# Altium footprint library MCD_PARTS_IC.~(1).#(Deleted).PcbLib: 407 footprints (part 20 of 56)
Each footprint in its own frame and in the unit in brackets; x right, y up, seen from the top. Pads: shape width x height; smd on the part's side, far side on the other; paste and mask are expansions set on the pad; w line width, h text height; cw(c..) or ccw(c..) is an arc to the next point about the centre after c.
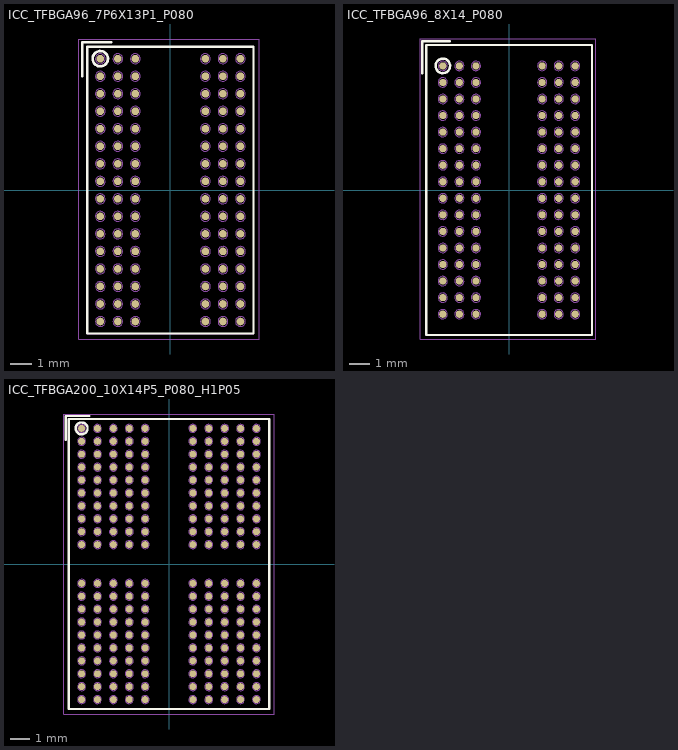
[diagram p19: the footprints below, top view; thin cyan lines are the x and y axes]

## ICC_TFBGA96_7P6X13P1_P080 [mm] "MCD-02775"
height 1.1
pads (96):
  round 0.35 smd mask+0.05: A1(-3.2,6) A2(-2.4,6) A3(-1.6,6) A7(1.6,6) A8(2.4,6) A9(3.2,6) B1(-3.2,5.2) B2(-2.4,5.2) B3(-1.6,5.2) B7(1.6,5.2) B8(2.4,5.2) B9(3.2,5.2) C1(-3.2,4.4) C2(-2.4,4.4) C3(-1.6,4.4) C7(1.6,4.4) C8(2.4,4.4) C9(3.2,4.4) D1(-3.2,3.6) D2(-2.4,3.6) D3(-1.6,3.6) D7(1.6,3.6) D8(2.4,3.6) D9(3.2,3.6) E1(-3.2,2.8) E2(-2.4,2.8) E3(-1.6,2.8) E7(1.6,2.8) E8(2.4,2.8) E9(3.2,2.8) F1(-3.2,2) F2(-2.4,2) F3(-1.6,2) F7(1.6,2) F8(2.4,2) F9(3.2,2) G1(-3.2,1.2) G2(-2.4,1.2) G3(-1.6,1.2) G7(1.6,1.2) G8(2.4,1.2) G9(3.2,1.2) H1(-3.2,0.4) H2(-2.4,0.4) H3(-1.6,0.4) H7(1.6,0.4) H8(2.4,0.4) H9(3.2,0.4) J1(-3.2,-0.4) J2(-2.4,-0.4) J3(-1.6,-0.4) J7(1.6,-0.4) J8(2.4,-0.4) J9(3.2,-0.4) K1(-3.2,-1.2) K2(-2.4,-1.2) K3(-1.6,-1.2) K7(1.6,-1.2) K8(2.4,-1.2) K9(3.2,-1.2) L1(-3.2,-2) L2(-2.4,-2) L3(-1.6,-2) L7(1.6,-2) L8(2.4,-2) L9(3.2,-2) M1(-3.2,-2.8) M2(-2.4,-2.8) M3(-1.6,-2.8) M7(1.6,-2.8) M8(2.4,-2.8) M9(3.2,-2.8) N1(-3.2,-3.6) N2(-2.4,-3.6) N3(-1.6,-3.6) N7(1.6,-3.6) N8(2.4,-3.6) N9(3.2,-3.6) P1(-3.2,-4.4) P2(-2.4,-4.4) P3(-1.6,-4.4) P7(1.6,-4.4) P8(2.4,-4.4) P9(3.2,-4.4) R1(-3.2,-5.2) R2(-2.4,-5.2) R3(-1.6,-5.2) R7(1.6,-5.2) R8(2.4,-5.2) R9(3.2,-5.2) T1(-3.2,-6) T2(-2.4,-6) T3(-1.6,-6) T7(1.6,-6) T8(2.4,-6) T9(3.2,-6)
Top Overlay:
  lines w0.1: -3.8,-6.55 -3.8,6.55 3.8,6.55 3.8,-6.55 -3.8,-6.55
  lines w0.12: -4.025,5.2 -4.025,6.75 -2.7,6.75 ; -2.851,6.023 ccw(c-3.2,6) -2.85,6
M14-Top Assembly:
  circle w0.01: c-3.2,6 r0.35
  circle w0.01: c-3.2,6 r0.225
  circle w0.01: c-2.4,6 r0.225
  circle w0.01: c-1.6,6 r0.225
  circle w0.01: c-3.2,-5.2 r0.225
  circle w0.01: c-2.4,-5.2 r0.225
  circle w0.01: c-1.6,-5.2 r0.225
  circle w0.01: c-1.6,-4.4 r0.225
  circle w0.01: c-2.4,-4.4 r0.225
  circle w0.01: c-3.2,-4.4 r0.225
  circle w0.01: c-1.6,-3.6 r0.225
  circle w0.01: c-2.4,-3.6 r0.225
  circle w0.01: c-3.2,-3.6 r0.225
  circle w0.01: c-1.6,-2.8 r0.225
  circle w0.01: c-2.4,-2.8 r0.225
  circle w0.01: c-3.2,-2.8 r0.225
  circle w0.01: c-1.6,-2 r0.225
  circle w0.01: c-2.4,-2 r0.225
  circle w0.01: c-3.2,-2 r0.225
  circle w0.01: c-1.6,-1.2 r0.225
  circle w0.01: c-2.4,-1.2 r0.225
  circle w0.01: c-3.2,-1.2 r0.225
  circle w0.01: c-1.6,-0.4 r0.225
  circle w0.01: c-2.4,-0.4 r0.225
  circle w0.01: c-3.2,-0.4 r0.225
  circle w0.01: c-1.6,0.4 r0.225
  circle w0.01: c-2.4,0.4 r0.225
  circle w0.01: c-3.2,0.4 r0.225
  circle w0.01: c-1.6,1.2 r0.225
  circle w0.01: c-2.4,1.2 r0.225
  circle w0.01: c-3.2,1.2 r0.225
  circle w0.01: c-1.6,2 r0.225
  circle w0.01: c-2.4,2 r0.225
  circle w0.01: c-3.2,2 r0.225
  circle w0.01: c-1.6,2.8 r0.225
  circle w0.01: c-2.4,2.8 r0.225
  circle w0.01: c-3.2,2.8 r0.225
  circle w0.01: c-1.6,3.6 r0.225
  circle w0.01: c-2.4,3.6 r0.225
  circle w0.01: c-3.2,3.6 r0.225
  circle w0.01: c-1.6,4.4 r0.225
  circle w0.01: c-2.4,4.4 r0.225
  circle w0.01: c-3.2,4.4 r0.225
  circle w0.01: c-1.6,5.2 r0.225
  circle w0.01: c-2.4,5.2 r0.225
  circle w0.01: c-3.2,5.2 r0.225
  circle w0.01: c1.6,6 r0.225
  circle w0.01: c2.4,6 r0.225
  circle w0.01: c3.2,6 r0.225
  circle w0.01: c1.6,-5.2 r0.225
  circle w0.01: c2.4,-5.2 r0.225
  circle w0.01: c3.2,-5.2 r0.225
  circle w0.01: c3.2,-4.4 r0.225
  circle w0.01: c2.4,-4.4 r0.225
  circle w0.01: c1.6,-4.4 r0.225
  circle w0.01: c3.2,-3.6 r0.225
  circle w0.01: c2.4,-3.6 r0.225
  circle w0.01: c1.6,-3.6 r0.225
  circle w0.01: c3.2,-2.8 r0.225
  circle w0.01: c2.4,-2.8 r0.225
  circle w0.01: c1.6,-2.8 r0.225
  circle w0.01: c3.2,-2 r0.225
  circle w0.01: c2.4,-2 r0.225
  circle w0.01: c1.6,-2 r0.225
  circle w0.01: c3.2,-1.2 r0.225
  circle w0.01: c2.4,-1.2 r0.225
  circle w0.01: c1.6,-1.2 r0.225
  circle w0.01: c3.2,-0.4 r0.225
  circle w0.01: c2.4,-0.4 r0.225
  circle w0.01: c1.6,-0.4 r0.225
  circle w0.01: c3.2,0.4 r0.225
  circle w0.01: c2.4,0.4 r0.225
  circle w0.01: c1.6,0.4 r0.225
  circle w0.01: c3.2,1.2 r0.225
  circle w0.01: c2.4,1.2 r0.225
  circle w0.01: c1.6,1.2 r0.225
  circle w0.01: c3.2,2 r0.225
  circle w0.01: c2.4,2 r0.225
  circle w0.01: c1.6,2 r0.225
  circle w0.01: c3.2,2.8 r0.225
  circle w0.01: c2.4,2.8 r0.225
  circle w0.01: c1.6,2.8 r0.225
  circle w0.01: c3.2,3.6 r0.225
  circle w0.01: c2.4,3.6 r0.225
  circle w0.01: c1.6,3.6 r0.225
  circle w0.01: c3.2,4.4 r0.225
  circle w0.01: c2.4,4.4 r0.225
  circle w0.01: c1.6,4.4 r0.225
  circle w0.01: c3.2,5.2 r0.225
  circle w0.01: c2.4,5.2 r0.225
  circle w0.01: c1.6,5.2 r0.225
  circle w0.01: c3.2,-6 r0.225
  circle w0.01: c2.4,-6 r0.225
  circle w0.01: c1.6,-6 r0.225
  circle w0.01: c-1.6,-6 r0.225
  circle w0.01: c-2.4,-6 r0.225
  circle w0.01: c-3.2,-6 r0.225
  lines w0.01: -3.8,-6.55 -3.8,6.55 3.8,6.55 3.8,-6.55 -3.8,-6.55
  text "'.Designator'" at -2,-0.5 h0.75
  text "A1" at -3.575,5.8 h0.75
M16-Top Courtyard:
  lines w0.01: -4.175,-6.8 4.05,-6.8 4.05,6.9 -4.175,6.9 -4.175,-6.8
3D body: height 1.21, standoff 1.2, extent -3.448,5.751 -2.95,6.25
3D body: height 1.2, standoff 0.4, extent -3.8,-6.55 3.8,6.55
3D body: height 0.5, standoff 0, extent -3.45,5.754 -2.95,6.246
3D body: height 0.5, standoff 0, extent -2.65,5.754 -2.15,6.246
3D body: height 0.5, standoff 0, extent -1.85,5.754 -1.35,6.246
3D body: height 0.5, standoff 0, extent 1.35,5.754 1.85,6.246
3D body: height 0.5, standoff 0, extent 2.15,5.754 2.65,6.246
3D body: height 0.5, standoff 0, extent 2.95,5.754 3.45,6.246
3D body: height 0.5, standoff 0, extent -3.45,4.954 -2.95,5.446
3D body: height 0.5, standoff 0, extent -2.65,4.954 -2.15,5.446
3D body: height 0.5, standoff 0, extent -1.85,4.954 -1.35,5.446
3D body: height 0.5, standoff 0, extent 1.35,4.954 1.85,5.446
3D body: height 0.5, standoff 0, extent 2.15,4.954 2.65,5.446
3D body: height 0.5, standoff 0, extent 2.95,4.954 3.45,5.446
3D body: height 0.5, standoff 0, extent -3.45,4.154 -2.95,4.646
3D body: height 0.5, standoff 0, extent -2.65,4.154 -2.15,4.646
3D body: height 0.5, standoff 0, extent -1.85,4.154 -1.35,4.646
3D body: height 0.5, standoff 0, extent 1.35,4.154 1.85,4.646
3D body: height 0.5, standoff 0, extent 2.15,4.154 2.65,4.646
3D body: height 0.5, standoff 0, extent 2.95,4.154 3.45,4.646
3D body: height 0.5, standoff 0, extent -3.45,3.354 -2.95,3.846
3D body: height 0.5, standoff 0, extent -2.65,3.354 -2.15,3.846
3D body: height 0.5, standoff 0, extent -1.85,3.354 -1.35,3.846
3D body: height 0.5, standoff 0, extent 1.35,3.354 1.85,3.846
3D body: height 0.5, standoff 0, extent 2.15,3.354 2.65,3.846
3D body: height 0.5, standoff 0, extent 2.95,3.354 3.45,3.846
3D body: height 0.5, standoff 0, extent -3.45,2.554 -2.95,3.046
3D body: height 0.5, standoff 0, extent -2.65,2.554 -2.15,3.046
3D body: height 0.5, standoff 0, extent -1.85,2.554 -1.35,3.046
3D body: height 0.5, standoff 0, extent 1.35,2.554 1.85,3.046
3D body: height 0.5, standoff 0, extent 2.15,2.554 2.65,3.046
3D body: height 0.5, standoff 0, extent 2.95,2.554 3.45,3.046
3D body: height 0.5, standoff 0, extent -3.45,1.754 -2.95,2.246
3D body: height 0.5, standoff 0, extent -2.65,1.754 -2.15,2.246
3D body: height 0.5, standoff 0, extent -1.85,1.754 -1.35,2.246
3D body: height 0.5, standoff 0, extent 1.35,1.754 1.85,2.246
3D body: height 0.5, standoff 0, extent 2.15,1.754 2.65,2.246
3D body: height 0.5, standoff 0, extent 2.95,1.754 3.45,2.246
3D body: height 0.5, standoff 0, extent -3.45,0.954 -2.95,1.446
3D body: height 0.5, standoff 0, extent -2.65,0.954 -2.15,1.446
3D body: height 0.5, standoff 0, extent -1.85,0.954 -1.35,1.446
3D body: height 0.5, standoff 0, extent 1.35,0.954 1.85,1.446
3D body: height 0.5, standoff 0, extent 2.15,0.954 2.65,1.446
3D body: height 0.5, standoff 0, extent 2.95,0.954 3.45,1.446
3D body: height 0.5, standoff 0, extent -3.45,0.154 -2.95,0.646
3D body: height 0.5, standoff 0, extent -2.65,0.154 -2.15,0.646
3D body: height 0.5, standoff 0, extent -1.85,0.154 -1.35,0.646
3D body: height 0.5, standoff 0, extent 1.35,0.154 1.85,0.646
3D body: height 0.5, standoff 0, extent 2.15,0.154 2.65,0.646
3D body: height 0.5, standoff 0, extent 2.95,0.154 3.45,0.646
3D body: height 0.5, standoff 0, extent -3.45,-0.646 -2.95,-0.154
3D body: height 0.5, standoff 0, extent -2.65,-0.646 -2.15,-0.154
3D body: height 0.5, standoff 0, extent -1.85,-0.646 -1.35,-0.154
3D body: height 0.5, standoff 0, extent 1.35,-0.646 1.85,-0.154
3D body: height 0.5, standoff 0, extent 2.15,-0.646 2.65,-0.154
3D body: height 0.5, standoff 0, extent 2.95,-0.646 3.45,-0.154
3D body: height 0.5, standoff 0, extent -3.45,-1.446 -2.95,-0.954
3D body: height 0.5, standoff 0, extent -2.65,-1.446 -2.15,-0.954
3D body: height 0.5, standoff 0, extent -1.85,-1.446 -1.35,-0.954
3D body: height 0.5, standoff 0, extent 1.35,-1.446 1.85,-0.954
3D body: height 0.5, standoff 0, extent 2.15,-1.446 2.65,-0.954
3D body: height 0.5, standoff 0, extent 2.95,-1.446 3.45,-0.954
3D body: height 0.5, standoff 0, extent -3.45,-2.246 -2.95,-1.754
3D body: height 0.5, standoff 0, extent -2.65,-2.246 -2.15,-1.754
3D body: height 0.5, standoff 0, extent -1.85,-2.246 -1.35,-1.754
3D body: height 0.5, standoff 0, extent 1.35,-2.246 1.85,-1.754
3D body: height 0.5, standoff 0, extent 2.15,-2.246 2.65,-1.754
3D body: height 0.5, standoff 0, extent 2.95,-2.246 3.45,-1.754
3D body: height 0.5, standoff 0, extent -3.45,-3.046 -2.95,-2.554
3D body: height 0.5, standoff 0, extent -2.65,-3.046 -2.15,-2.554
3D body: height 0.5, standoff 0, extent -1.85,-3.046 -1.35,-2.554
3D body: height 0.5, standoff 0, extent 1.35,-3.046 1.85,-2.554
3D body: height 0.5, standoff 0, extent 2.15,-3.046 2.65,-2.554
3D body: height 0.5, standoff 0, extent 2.95,-3.046 3.45,-2.554
3D body: height 0.5, standoff 0, extent -3.45,-3.846 -2.95,-3.354
3D body: height 0.5, standoff 0, extent -2.65,-3.846 -2.15,-3.354
3D body: height 0.5, standoff 0, extent -1.85,-3.846 -1.35,-3.354
3D body: height 0.5, standoff 0, extent 1.35,-3.846 1.85,-3.354
3D body: height 0.5, standoff 0, extent 2.15,-3.846 2.65,-3.354
3D body: height 0.5, standoff 0, extent 2.95,-3.846 3.45,-3.354
3D body: height 0.5, standoff 0, extent -3.45,-4.646 -2.95,-4.154
3D body: height 0.5, standoff 0, extent -2.65,-4.646 -2.15,-4.154
3D body: height 0.5, standoff 0, extent -1.85,-4.646 -1.35,-4.154
3D body: height 0.5, standoff 0, extent 1.35,-4.646 1.85,-4.154
3D body: height 0.5, standoff 0, extent 2.15,-4.646 2.65,-4.154
3D body: height 0.5, standoff 0, extent 2.95,-4.646 3.45,-4.154
3D body: height 0.5, standoff 0, extent -3.45,-5.446 -2.95,-4.954
3D body: height 0.5, standoff 0, extent -2.65,-5.446 -2.15,-4.954
3D body: height 0.5, standoff 0, extent -1.85,-5.446 -1.35,-4.954
3D body: height 0.5, standoff 0, extent 1.35,-5.446 1.85,-4.954
3D body: height 0.5, standoff 0, extent 2.15,-5.446 2.65,-4.954
3D body: height 0.5, standoff 0, extent 2.95,-5.446 3.45,-4.954
3D body: height 0.5, standoff 0, extent -3.45,-6.246 -2.95,-5.754
3D body: height 0.5, standoff 0, extent -2.65,-6.246 -2.15,-5.754
3D body: height 0.5, standoff 0, extent -1.85,-6.246 -1.35,-5.754
3D body: height 0.5, standoff 0, extent 1.35,-6.246 1.85,-5.754
3D body: height 0.5, standoff 0, extent 2.15,-6.246 2.65,-5.754
3D body: height 0.5, standoff 0, extent 2.95,-6.246 3.45,-5.754

## ICC_TFBGA96_8X14_P080 [mm] "MCD-02181"
height 1.1
pads (96):
  round 0.35 smd mask+0.05: A1(-3.2,6) A2(-2.4,6) A3(-1.6,6) A7(1.6,6) A8(2.4,6) A9(3.2,6) B1(-3.2,5.2) B2(-2.4,5.2) B3(-1.6,5.2) B7(1.6,5.2) B8(2.4,5.2) B9(3.2,5.2) C1(-3.2,4.4) C2(-2.4,4.4) C3(-1.6,4.4) C7(1.6,4.4) C8(2.4,4.4) C9(3.2,4.4) D1(-3.2,3.6) D2(-2.4,3.6) D3(-1.6,3.6) D7(1.6,3.6) D8(2.4,3.6) D9(3.2,3.6) E1(-3.2,2.8) E2(-2.4,2.8) E3(-1.6,2.8) E7(1.6,2.8) E8(2.4,2.8) E9(3.2,2.8) F1(-3.2,2) F2(-2.4,2) F3(-1.6,2) F7(1.6,2) F8(2.4,2) F9(3.2,2) G1(-3.2,1.2) G2(-2.4,1.2) G3(-1.6,1.2) G7(1.6,1.2) G8(2.4,1.2) G9(3.2,1.2) H1(-3.2,0.4) H2(-2.4,0.4) H3(-1.6,0.4) H7(1.6,0.4) H8(2.4,0.4) H9(3.2,0.4) J1(-3.2,-0.4) J2(-2.4,-0.4) J3(-1.6,-0.4) J7(1.6,-0.4) J8(2.4,-0.4) J9(3.2,-0.4) K1(-3.2,-1.2) K2(-2.4,-1.2) K3(-1.6,-1.2) K7(1.6,-1.2) K8(2.4,-1.2) K9(3.2,-1.2) L1(-3.2,-2) L2(-2.4,-2) L3(-1.6,-2) L7(1.6,-2) L8(2.4,-2) L9(3.2,-2) M1(-3.2,-2.8) M2(-2.4,-2.8) M3(-1.6,-2.8) M7(1.6,-2.8) M8(2.4,-2.8) M9(3.2,-2.8) N1(-3.2,-3.6) N2(-2.4,-3.6) N3(-1.6,-3.6) N7(1.6,-3.6) N8(2.4,-3.6) N9(3.2,-3.6) P1(-3.2,-4.4) P2(-2.4,-4.4) P3(-1.6,-4.4) P7(1.6,-4.4) P8(2.4,-4.4) P9(3.2,-4.4) R1(-3.2,-5.2) R2(-2.4,-5.2) R3(-1.6,-5.2) R7(1.6,-5.2) R8(2.4,-5.2) R9(3.2,-5.2) T1(-3.2,-6) T2(-2.4,-6) T3(-1.6,-6) T7(1.6,-6) T8(2.4,-6) T9(3.2,-6)
Top Overlay:
  lines w0.1: -4,-7 -4,7 4,7 4,-7 -4,-7
  lines w0.12: -4.2,5.65 -4.2,7.2 -2.875,7.2 ; -2.851,6.023 ccw(c-3.2,6) -2.85,6
M14-Top Assembly:
  circle w0.01: c-3.2,-6 r0.225
  circle w0.01: c-2.4,-6 r0.225
  circle w0.01: c-1.6,-6 r0.225
  circle w0.01: c1.6,-6 r0.225
  circle w0.01: c2.4,-6 r0.225
  circle w0.01: c3.2,-6 r0.225
  circle w0.01: c1.6,5.2 r0.225
  circle w0.01: c2.4,5.2 r0.225
  circle w0.01: c3.2,5.2 r0.225
  circle w0.01: c1.6,4.4 r0.225
  circle w0.01: c2.4,4.4 r0.225
  circle w0.01: c3.2,4.4 r0.225
  circle w0.01: c1.6,3.6 r0.225
  circle w0.01: c2.4,3.6 r0.225
  circle w0.01: c3.2,3.6 r0.225
  circle w0.01: c1.6,2.8 r0.225
  circle w0.01: c2.4,2.8 r0.225
  circle w0.01: c3.2,2.8 r0.225
  circle w0.01: c1.6,2 r0.225
  circle w0.01: c2.4,2 r0.225
  circle w0.01: c3.2,2 r0.225
  circle w0.01: c1.6,1.2 r0.225
  circle w0.01: c2.4,1.2 r0.225
  circle w0.01: c3.2,1.2 r0.225
  circle w0.01: c1.6,0.4 r0.225
  circle w0.01: c2.4,0.4 r0.225
  circle w0.01: c3.2,0.4 r0.225
  circle w0.01: c1.6,-0.4 r0.225
  circle w0.01: c2.4,-0.4 r0.225
  circle w0.01: c3.2,-0.4 r0.225
  circle w0.01: c1.6,-1.2 r0.225
  circle w0.01: c2.4,-1.2 r0.225
  circle w0.01: c3.2,-1.2 r0.225
  circle w0.01: c1.6,-2 r0.225
  circle w0.01: c2.4,-2 r0.225
  circle w0.01: c3.2,-2 r0.225
  circle w0.01: c1.6,-2.8 r0.225
  circle w0.01: c2.4,-2.8 r0.225
  circle w0.01: c3.2,-2.8 r0.225
  circle w0.01: c1.6,-3.6 r0.225
  circle w0.01: c2.4,-3.6 r0.225
  circle w0.01: c3.2,-3.6 r0.225
  circle w0.01: c1.6,-4.4 r0.225
  circle w0.01: c2.4,-4.4 r0.225
  circle w0.01: c3.2,-4.4 r0.225
  circle w0.01: c3.2,-5.2 r0.225
  circle w0.01: c2.4,-5.2 r0.225
  circle w0.01: c1.6,-5.2 r0.225
  circle w0.01: c3.2,6 r0.225
  circle w0.01: c2.4,6 r0.225
  circle w0.01: c1.6,6 r0.225
  circle w0.01: c-3.2,5.2 r0.225
  circle w0.01: c-2.4,5.2 r0.225
  circle w0.01: c-1.6,5.2 r0.225
  circle w0.01: c-3.2,4.4 r0.225
  circle w0.01: c-2.4,4.4 r0.225
  circle w0.01: c-1.6,4.4 r0.225
  circle w0.01: c-3.2,3.6 r0.225
  circle w0.01: c-2.4,3.6 r0.225
  circle w0.01: c-1.6,3.6 r0.225
  circle w0.01: c-3.2,2.8 r0.225
  circle w0.01: c-2.4,2.8 r0.225
  circle w0.01: c-1.6,2.8 r0.225
  circle w0.01: c-3.2,2 r0.225
  circle w0.01: c-2.4,2 r0.225
  circle w0.01: c-1.6,2 r0.225
  circle w0.01: c-3.2,1.2 r0.225
  circle w0.01: c-2.4,1.2 r0.225
  circle w0.01: c-1.6,1.2 r0.225
  circle w0.01: c-3.2,0.4 r0.225
  circle w0.01: c-2.4,0.4 r0.225
  circle w0.01: c-1.6,0.4 r0.225
  circle w0.01: c-3.2,-0.4 r0.225
  circle w0.01: c-2.4,-0.4 r0.225
  circle w0.01: c-1.6,-0.4 r0.225
  circle w0.01: c-3.2,-1.2 r0.225
  circle w0.01: c-2.4,-1.2 r0.225
  circle w0.01: c-1.6,-1.2 r0.225
  circle w0.01: c-3.2,-2 r0.225
  circle w0.01: c-2.4,-2 r0.225
  circle w0.01: c-1.6,-2 r0.225
  circle w0.01: c-3.2,-2.8 r0.225
  circle w0.01: c-2.4,-2.8 r0.225
  circle w0.01: c-1.6,-2.8 r0.225
  circle w0.01: c-3.2,-3.6 r0.225
  circle w0.01: c-2.4,-3.6 r0.225
  circle w0.01: c-1.6,-3.6 r0.225
  circle w0.01: c-3.2,-4.4 r0.225
  circle w0.01: c-2.4,-4.4 r0.225
  circle w0.01: c-1.6,-4.4 r0.225
  circle w0.01: c-1.6,-5.2 r0.225
  circle w0.01: c-2.4,-5.2 r0.225
  circle w0.01: c-3.2,-5.2 r0.225
  circle w0.01: c-1.6,6 r0.225
  circle w0.01: c-2.4,6 r0.225
  circle w0.01: c-3.2,6 r0.225
  circle w0.01: c-3.2,6 r0.35
  lines w0.01: -4,-7 4,-7 4,7 -4,7 -4,-7
  text "A1" at -3.575,5.8 h0.75
  text "'.Designator'" at -2,-0.5 h0.75
M16-Top Courtyard:
  lines w0.01: -4.3,-7.2 -4.3,7.3 4.2,7.3 4.2,-7.2 -4.3,-7.2
3D body: height 1.2, standoff 0, extent -4,-7 4,7
3D body: height 1.21, standoff 1.2, extent -3.448,5.751 -2.95,6.25

## ICC_TFBGA200_10X14P5_P080_H1P05 [mm]
height 1.05
pads (200):
  round 0.35 smd mask+0.05: A1(-4.4,6.825) A2(-3.6,6.825) A3(-2.8,6.825) A4(-2,6.825) A5(-1.2,6.825) A8(1.2,6.825) A9(2,6.825) A10(2.8,6.825) A11(3.6,6.825) A12(4.4,6.825) AA1(-4.4,-6.175) AA2(-3.6,-6.175) AA3(-2.8,-6.175) AA4(-2,-6.175) AA5(-1.2,-6.175) AA8(1.2,-6.175) AA9(2,-6.175) AA10(2.8,-6.175) AA11(3.6,-6.175) AA12(4.4,-6.175) AB1(-4.4,-6.825) AB2(-3.6,-6.825) AB3(-2.8,-6.825) AB4(-2,-6.825) AB5(-1.2,-6.825) AB8(1.2,-6.825) AB9(2,-6.825) AB10(2.8,-6.825) AB11(3.6,-6.825) AB12(4.4,-6.825) B1(-4.4,6.175) B2(-3.6,6.175) B3(-2.8,6.175) B4(-2,6.175) B5(-1.2,6.175) B8(1.2,6.175) B9(2,6.175) B10(2.8,6.175) B11(3.6,6.175) B12(4.4,6.175) C1(-4.4,5.525) C2(-3.6,5.525) C3(-2.8,5.525) C4(-2,5.525) C5(-1.2,5.525) C8(1.2,5.525) C9(2,5.525) C10(2.8,5.525) C11(3.6,5.525) C12(4.4,5.525) D1(-4.4,4.875) D2(-3.6,4.875) D3(-2.8,4.875) D4(-2,4.875) D5(-1.2,4.875) D8(1.2,4.875) D9(2,4.875) D10(2.8,4.875) D11(3.6,4.875) D12(4.4,4.875) E1(-4.4,4.225) E2(-3.6,4.225) E3(-2.8,4.225) E4(-2,4.225) E5(-1.2,4.225) E8(1.2,4.225) E9(2,4.225) E10(2.8,4.225) E11(3.6,4.225) E12(4.4,4.225) F1(-4.4,3.575) F2(-3.6,3.575) F3(-2.8,3.575) F4(-2,3.575) F5(-1.2,3.575) F8(1.2,3.575) F9(2,3.575) F10(2.8,3.575) F11(3.6,3.575) F12(4.4,3.575) G1(-4.4,2.925) G2(-3.6,2.925) G3(-2.8,2.925) G4(-2,2.925) G5(-1.2,2.925) G8(1.2,2.925) G9(2,2.925) G10(2.8,2.925) G11(3.6,2.925) G12(4.4,2.925) H1(-4.4,2.275) H2(-3.6,2.275) H3(-2.8,2.275) H4(-2,2.275) H5(-1.2,2.275) H8(1.2,2.275) H9(2,2.275) H10(2.8,2.275) H11(3.6,2.275) H12(4.4,2.275) J1(-4.4,1.625) J2(-3.6,1.625) J3(-2.8,1.625) J4(-2,1.625) J5(-1.2,1.625) J8(1.2,1.625) J9(2,1.625) J10(2.8,1.625) J11(3.6,1.625) J12(4.4,1.625) K1(-4.4,0.975) K2(-3.6,0.975) K3(-2.8,0.975) K4(-2,0.975) K5(-1.2,0.975) K8(1.2,0.975) K9(2,0.975) K10(2.8,0.975) K11(3.6,0.975) K12(4.4,0.975) N1(-4.4,-0.975) N2(-3.6,-0.975) N3(-2.8,-0.975) N4(-2,-0.975) N5(-1.2,-0.975) N8(1.2,-0.975) N9(2,-0.975) N10(2.8,-0.975) N11(3.6,-0.975) N12(4.4,-0.975) P1(-4.4,-1.625) P2(-3.6,-1.625) P3(-2.8,-1.625) P4(-2,-1.625) P5(-1.2,-1.625) P8(1.2,-1.625) P9(2,-1.625) P10(2.8,-1.625) P11(3.6,-1.625) P12(4.4,-1.625) R1(-4.4,-2.275) R2(-3.6,-2.275) R3(-2.8,-2.275) R4(-2,-2.275) R5(-1.2,-2.275) R8(1.2,-2.275) R9(2,-2.275) R10(2.8,-2.275) R11(3.6,-2.275) R12(4.4,-2.275) T1(-4.4,-2.925) T2(-3.6,-2.925) T3(-2.8,-2.925) T4(-2,-2.925) T5(-1.2,-2.925) T8(1.2,-2.925) T9(2,-2.925) T10(2.8,-2.925) T11(3.6,-2.925) T12(4.4,-2.925) U1(-4.4,-3.575) U2(-3.6,-3.575) U3(-2.8,-3.575) U4(-2,-3.575) U5(-1.2,-3.575) U8(1.2,-3.575) U9(2,-3.575) U10(2.8,-3.575) U11(3.6,-3.575) U12(4.4,-3.575) V1(-4.4,-4.225) V2(-3.6,-4.225) V3(-2.8,-4.225) V4(-2,-4.225) V5(-1.2,-4.225) V8(1.2,-4.225) V9(2,-4.225) V10(2.8,-4.225) V11(3.6,-4.225) V12(4.4,-4.225) W1(-4.4,-4.875) W2(-3.6,-4.875) W3(-2.8,-4.875) W4(-2,-4.875) W5(-1.2,-4.875) W8(1.2,-4.875) W9(2,-4.875) W10(2.8,-4.875) W11(3.6,-4.875) W12(4.4,-4.875) Y1(-4.4,-5.525) Y2(-3.6,-5.525) Y3(-2.8,-5.525) Y4(-2,-5.525) Y5(-1.2,-5.525) Y8(1.2,-5.525) Y9(2,-5.525) Y10(2.8,-5.525) Y11(3.6,-5.525) Y12(4.4,-5.525)
Top Overlay:
  circle w0.12: c-4.4,6.825 r0.3
  lines w0.12: -5.2,6.25 -5.2,7.45 -4,7.45 ; -5.05,-7.3 -5.05,7.3 5.05,7.3 5.05,-7.3 -5.05,-7.3
M14-Top Assembly:
  drawing of 204 lines, arcs and shapes, not listed
  text "A5" at -1.525,6.65 h0.4
  text "AB12" at 3.675,-7 h0.4
  text "AB8" at 0.7,-7 h0.4
  text "AB5" at -1.7,-7 h0.4
  text "AB1" at -4.825,-7 h0.4
  text "N12" at 3.925,-1.15 h0.4
  text "N8" at 0.875,-1.15 h0.4
  text "N5" at -1.525,-1.15 h0.4
  text "N1" at -4.65,-1.15 h0.4
  text "K12" at 3.95,0.8 h0.4
  text "K8" at 0.875,0.8 h0.4
  text "K5" at -1.5,0.8 h0.4
  text "K1" at -4.625,0.8 h0.4
  text "A12" at 3.925,6.65 h0.4
  text "A8" at 0.875,6.65 h0.4
  text "'.Designator'" at 0,0 h0.75
  text "A1" at -4.65,6.65 h0.4
M16-Top Courtyard:
  lines w0.01: -5.3,-7.55 5.3,-7.55 5.3,7.55 -5.3,7.55 -5.3,-7.55
3D body: height 0.36, standoff -0.04, extent 4.201,-7.022 4.6,-6.628
3D body: height 0.36, standoff -0.04, extent 3.401,-7.022 3.8,-6.628
3D body: height 0.36, standoff -0.04, extent 1.001,-7.022 1.4,-6.628
3D body: height 0.36, standoff -0.04, extent 1.801,-7.022 2.2,-6.628
3D body: height 0.36, standoff -0.04, extent 2.601,-7.022 3,-6.628
3D body: height 0.36, standoff -0.04, extent -4.599,-7.022 -4.2,-6.628
3D body: height 0.36, standoff -0.04, extent -3.799,-7.022 -3.4,-6.628
3D body: height 0.36, standoff -0.04, extent -2.999,-7.022 -2.6,-6.628
3D body: height 0.36, standoff -0.04, extent -2.199,-7.022 -1.8,-6.628
3D body: height 0.36, standoff -0.04, extent -1.399,-7.022 -1,-6.628
3D body: height 0.36, standoff -0.04, extent 4.201,-6.372 4.6,-5.978
3D body: height 0.36, standoff -0.04, extent 3.401,-6.372 3.8,-5.978
3D body: height 0.36, standoff -0.04, extent 1.001,-6.372 1.4,-5.978
3D body: height 0.36, standoff -0.04, extent 1.801,-6.372 2.2,-5.978
3D body: height 0.36, standoff -0.04, extent 2.601,-6.372 3,-5.978
3D body: height 0.36, standoff -0.04, extent -4.599,-6.372 -4.2,-5.978
3D body: height 0.36, standoff -0.04, extent -3.799,-6.372 -3.4,-5.978
3D body: height 0.36, standoff -0.04, extent -2.999,-6.372 -2.6,-5.978
3D body: height 0.36, standoff -0.04, extent -2.199,-6.372 -1.8,-5.978
3D body: height 0.36, standoff -0.04, extent -1.399,-6.372 -1,-5.978
3D body: height 0.36, standoff -0.04, extent 4.201,-5.722 4.6,-5.328
3D body: height 0.36, standoff -0.04, extent 3.401,-5.722 3.8,-5.328
3D body: height 0.36, standoff -0.04, extent 1.001,-5.722 1.4,-5.328
3D body: height 0.36, standoff -0.04, extent 1.801,-5.722 2.2,-5.328
3D body: height 0.36, standoff -0.04, extent 2.601,-5.722 3,-5.328
3D body: height 0.36, standoff -0.04, extent -4.599,-5.722 -4.2,-5.328
3D body: height 0.36, standoff -0.04, extent -3.799,-5.722 -3.4,-5.328
3D body: height 0.36, standoff -0.04, extent -2.999,-5.722 -2.6,-5.328
3D body: height 0.36, standoff -0.04, extent -2.199,-5.722 -1.8,-5.328
3D body: height 0.36, standoff -0.04, extent -1.399,-5.722 -1,-5.328
3D body: height 0.36, standoff -0.04, extent 4.201,-5.072 4.6,-4.678
3D body: height 0.36, standoff -0.04, extent 3.401,-5.072 3.8,-4.678
3D body: height 0.36, standoff -0.04, extent 1.001,-5.072 1.4,-4.678
3D body: height 0.36, standoff -0.04, extent 1.801,-5.072 2.2,-4.678
3D body: height 0.36, standoff -0.04, extent 2.601,-5.072 3,-4.678
3D body: height 0.36, standoff -0.04, extent -4.599,-5.072 -4.2,-4.678
3D body: height 0.36, standoff -0.04, extent -3.799,-5.072 -3.4,-4.678
3D body: height 0.36, standoff -0.04, extent -2.999,-5.072 -2.6,-4.678
3D body: height 0.36, standoff -0.04, extent -2.199,-5.072 -1.8,-4.678
3D body: height 0.36, standoff -0.04, extent -1.399,-5.072 -1,-4.678
3D body: height 0.36, standoff -0.04, extent 4.201,-4.422 4.6,-4.028
3D body: height 0.36, standoff -0.04, extent 3.401,-4.422 3.8,-4.028
3D body: height 0.36, standoff -0.04, extent 1.001,-4.422 1.4,-4.028
3D body: height 0.36, standoff -0.04, extent 1.801,-4.422 2.2,-4.028
3D body: height 0.36, standoff -0.04, extent 2.601,-4.422 3,-4.028
3D body: height 0.36, standoff -0.04, extent -4.599,-4.422 -4.2,-4.028
3D body: height 0.36, standoff -0.04, extent -3.799,-4.422 -3.4,-4.028
3D body: height 0.36, standoff -0.04, extent -2.999,-4.422 -2.6,-4.028
3D body: height 0.36, standoff -0.04, extent -2.199,-4.422 -1.8,-4.028
3D body: height 0.36, standoff -0.04, extent -1.399,-4.422 -1,-4.028
3D body: height 0.36, standoff -0.04, extent 4.201,2.728 4.6,3.122
3D body: height 0.36, standoff -0.04, extent 4.201,2.078 4.6,2.472
3D body: height 0.36, standoff -0.04, extent 4.201,1.428 4.6,1.822
3D body: height 0.36, standoff -0.04, extent 4.201,0.778 4.6,1.172
3D body: height 0.36, standoff -0.04, extent 2.601,3.378 3,3.772
3D body: height 0.36, standoff -0.04, extent 1.801,3.378 2.2,3.772
3D body: height 0.36, standoff -0.04, extent 1.001,3.378 1.4,3.772
3D body: height 0.36, standoff -0.04, extent 3.401,3.378 3.8,3.772
3D body: height 0.36, standoff -0.04, extent 4.201,3.378 4.6,3.772
3D body: height 0.36, standoff -0.04, extent 4.201,-3.772 4.6,-3.378
3D body: height 0.36, standoff -0.04, extent 3.401,-3.772 3.8,-3.378
3D body: height 0.36, standoff -0.04, extent 1.001,-3.772 1.4,-3.378
3D body: height 0.36, standoff -0.04, extent 1.801,-3.772 2.2,-3.378
3D body: height 0.36, standoff -0.04, extent 2.601,-3.772 3,-3.378
3D body: height 0.36, standoff -0.04, extent -4.599,-3.772 -4.2,-3.378
3D body: height 0.36, standoff -0.04, extent -3.799,-3.772 -3.4,-3.378
3D body: height 0.36, standoff -0.04, extent -2.999,-3.772 -2.6,-3.378
3D body: height 0.36, standoff -0.04, extent -2.199,-3.772 -1.8,-3.378
3D body: height 0.36, standoff -0.04, extent -1.399,-3.772 -1,-3.378
3D body: height 0.36, standoff -0.04, extent 4.201,-3.122 4.6,-2.728
3D body: height 0.36, standoff -0.04, extent 3.401,-3.122 3.8,-2.728
3D body: height 0.36, standoff -0.04, extent 1.001,-3.122 1.4,-2.728
3D body: height 0.36, standoff -0.04, extent 1.801,-3.122 2.2,-2.728
3D body: height 0.36, standoff -0.04, extent 2.601,-3.122 3,-2.728
3D body: height 0.36, standoff -0.04, extent -4.599,-3.122 -4.2,-2.728
3D body: height 0.36, standoff -0.04, extent -3.799,-3.122 -3.4,-2.728
3D body: height 0.36, standoff -0.04, extent -2.999,-3.122 -2.6,-2.728
3D body: height 0.36, standoff -0.04, extent -2.199,-3.122 -1.8,-2.728
3D body: height 0.36, standoff -0.04, extent -1.399,-3.122 -1,-2.728
3D body: height 1.05, standoff 0.3, extent -5.05,-7.3 5.05,7.3
3D body: height 0.36, standoff -0.04, extent 4.201,6.628 4.6,7.022
3D body: height 0.36, standoff -0.04, extent 3.401,6.628 3.8,7.022
3D body: height 0.36, standoff -0.04, extent 1.001,6.628 1.4,7.022
3D body: height 0.36, standoff -0.04, extent 1.801,6.628 2.2,7.022
3D body: height 0.36, standoff -0.04, extent 2.601,6.628 3,7.022
3D body: height 0.36, standoff -0.04, extent -4.599,6.628 -4.2,7.022
3D body: height 0.36, standoff -0.04, extent -3.799,6.628 -3.4,7.022
3D body: height 0.36, standoff -0.04, extent -2.999,6.628 -2.6,7.022
3D body: height 0.36, standoff -0.04, extent -2.199,6.628 -1.8,7.022
3D body: height 0.36, standoff -0.04, extent -1.399,6.628 -1,7.022
3D body: height 0.36, standoff -0.04, extent -1.399,5.978 -1,6.372
3D body: height 0.36, standoff -0.04, extent -2.199,5.978 -1.8,6.372
3D body: height 0.36, standoff -0.04, extent -2.999,5.978 -2.6,6.372
3D body: height 0.36, standoff -0.04, extent -3.799,5.978 -3.4,6.372
3D body: height 0.36, standoff -0.04, extent -4.599,5.978 -4.2,6.372
3D body: height 0.36, standoff -0.04, extent 2.601,5.978 3,6.372
3D body: height 0.36, standoff -0.04, extent 1.801,5.978 2.2,6.372
3D body: height 0.36, standoff -0.04, extent 1.001,5.978 1.4,6.372
3D body: height 0.36, standoff -0.04, extent 3.401,5.978 3.8,6.372
3D body: height 0.36, standoff -0.04, extent 4.201,5.978 4.6,6.372
3D body: height 0.36, standoff -0.04, extent -1.399,5.328 -1,5.722
3D body: height 0.36, standoff -0.04, extent -2.199,5.328 -1.8,5.722
3D body: height 0.36, standoff -0.04, extent -2.999,5.328 -2.6,5.722
3D body: height 0.36, standoff -0.04, extent -3.799,5.328 -3.4,5.722
3D body: height 0.36, standoff -0.04, extent -4.599,5.328 -4.2,5.722
3D body: height 0.36, standoff -0.04, extent 2.601,5.328 3,5.722
3D body: height 0.36, standoff -0.04, extent 1.801,5.328 2.2,5.722
3D body: height 0.36, standoff -0.04, extent 1.001,5.328 1.4,5.722
3D body: height 0.36, standoff -0.04, extent 3.401,5.328 3.8,5.722
3D body: height 0.36, standoff -0.04, extent 4.201,5.328 4.6,5.722
3D body: height 0.36, standoff -0.04, extent -1.399,4.678 -1,5.072
3D body: height 0.36, standoff -0.04, extent -2.199,4.678 -1.8,5.072
3D body: height 0.36, standoff -0.04, extent -2.999,4.678 -2.6,5.072
3D body: height 0.36, standoff -0.04, extent -3.799,4.678 -3.4,5.072
3D body: height 0.36, standoff -0.04, extent -4.599,4.678 -4.2,5.072
3D body: height 0.36, standoff -0.04, extent 2.601,4.678 3,5.072
3D body: height 0.36, standoff -0.04, extent 1.801,4.678 2.2,5.072
3D body: height 0.36, standoff -0.04, extent 1.001,4.678 1.4,5.072
3D body: height 0.36, standoff -0.04, extent 3.401,4.678 3.8,5.072
3D body: height 0.36, standoff -0.04, extent 4.201,4.678 4.6,5.072
3D body: height 0.36, standoff -0.04, extent -1.399,4.028 -1,4.422
3D body: height 0.36, standoff -0.04, extent -2.199,4.028 -1.8,4.422
3D body: height 0.36, standoff -0.04, extent -2.999,4.028 -2.6,4.422
3D body: height 0.36, standoff -0.04, extent -3.799,4.028 -3.4,4.422
3D body: height 0.36, standoff -0.04, extent -4.599,4.028 -4.2,4.422
3D body: height 0.36, standoff -0.04, extent 2.601,4.028 3,4.422
3D body: height 0.36, standoff -0.04, extent 1.801,4.028 2.2,4.422
3D body: height 0.36, standoff -0.04, extent 1.001,4.028 1.4,4.422
3D body: height 0.36, standoff -0.04, extent 3.401,4.028 3.8,4.422
3D body: height 0.36, standoff -0.04, extent 4.201,4.028 4.6,4.422
3D body: height 0.36, standoff -0.04, extent -1.399,3.378 -1,3.772
3D body: height 0.36, standoff -0.04, extent -2.199,3.378 -1.8,3.772
3D body: height 0.36, standoff -0.04, extent -2.999,3.378 -2.6,3.772
3D body: height 0.36, standoff -0.04, extent -3.799,3.378 -3.4,3.772
3D body: height 0.36, standoff -0.04, extent -4.599,3.378 -4.2,3.772
3D body: height 0.36, standoff -0.04, extent -1.399,2.728 -1,3.122
3D body: height 0.36, standoff -0.04, extent -2.199,2.728 -1.8,3.122
3D body: height 0.36, standoff -0.04, extent -2.999,2.728 -2.6,3.122
3D body: height 0.36, standoff -0.04, extent -3.799,2.728 -3.4,3.122
3D body: height 0.36, standoff -0.04, extent -4.599,2.728 -4.2,3.122
3D body: height 0.36, standoff -0.04, extent 2.601,2.728 3,3.122
3D body: height 0.36, standoff -0.04, extent 1.801,2.728 2.2,3.122
3D body: height 0.36, standoff -0.04, extent 1.001,2.728 1.4,3.122
3D body: height 0.36, standoff -0.04, extent 3.401,2.728 3.8,3.122
3D body: height 0.36, standoff -0.04, extent -1.399,2.078 -1,2.472
3D body: height 0.36, standoff -0.04, extent -2.199,2.078 -1.8,2.472
3D body: height 0.36, standoff -0.04, extent -2.999,2.078 -2.6,2.472
3D body: height 0.36, standoff -0.04, extent -3.799,2.078 -3.4,2.472
3D body: height 0.36, standoff -0.04, extent -4.599,2.078 -4.2,2.472
3D body: height 0.36, standoff -0.04, extent 2.601,2.078 3,2.472
3D body: height 0.36, standoff -0.04, extent 1.801,2.078 2.2,2.472
3D body: height 0.36, standoff -0.04, extent 1.001,2.078 1.4,2.472
3D body: height 0.36, standoff -0.04, extent 3.401,2.078 3.8,2.472
3D body: height 0.36, standoff -0.04, extent -1.399,1.428 -1,1.822
3D body: height 0.36, standoff -0.04, extent -2.199,1.428 -1.8,1.822
3D body: height 0.36, standoff -0.04, extent -2.999,1.428 -2.6,1.822
3D body: height 0.36, standoff -0.04, extent -3.799,1.428 -3.4,1.822
3D body: height 0.36, standoff -0.04, extent -4.599,1.428 -4.2,1.822
3D body: height 0.36, standoff -0.04, extent 2.601,1.428 3,1.822
3D body: height 0.36, standoff -0.04, extent 1.801,1.428 2.2,1.822
3D body: height 0.36, standoff -0.04, extent 1.001,1.428 1.4,1.822
3D body: height 0.36, standoff -0.04, extent 3.401,1.428 3.8,1.822
3D body: height 0.36, standoff -0.04, extent -1.399,0.778 -1,1.172
3D body: height 0.36, standoff -0.04, extent -2.199,0.778 -1.8,1.172
3D body: height 0.36, standoff -0.04, extent -2.999,0.778 -2.6,1.172
3D body: height 0.36, standoff -0.04, extent -3.799,0.778 -3.4,1.172
3D body: height 0.36, standoff -0.04, extent -4.599,0.778 -4.2,1.172
3D body: height 0.36, standoff -0.04, extent 2.601,0.778 3,1.172
3D body: height 0.36, standoff -0.04, extent 1.801,0.778 2.2,1.172
3D body: height 0.36, standoff -0.04, extent 1.001,0.778 1.4,1.172
3D body: height 0.36, standoff -0.04, extent 3.401,0.778 3.8,1.172
3D body: height 0.36, standoff -0.04, extent -1.399,-1.172 -1,-0.778
3D body: height 0.36, standoff -0.04, extent -2.199,-1.172 -1.8,-0.778
3D body: height 0.36, standoff -0.04, extent -2.999,-1.172 -2.6,-0.778
3D body: height 0.36, standoff -0.04, extent -3.799,-1.172 -3.4,-0.778
3D body: height 0.36, standoff -0.04, extent -4.599,-1.172 -4.2,-0.778
3D body: height 0.36, standoff -0.04, extent 2.601,-1.172 3,-0.778
3D body: height 0.36, standoff -0.04, extent 1.801,-1.172 2.2,-0.778
3D body: height 0.36, standoff -0.04, extent 1.001,-1.172 1.4,-0.778
3D body: height 0.36, standoff -0.04, extent 3.401,-1.172 3.8,-0.778
3D body: height 0.36, standoff -0.04, extent 4.201,-1.172 4.6,-0.778
3D body: height 0.36, standoff -0.04, extent -1.399,-1.822 -1,-1.428
3D body: height 0.36, standoff -0.04, extent -2.199,-1.822 -1.8,-1.428
3D body: height 0.36, standoff -0.04, extent -2.999,-1.822 -2.6,-1.428
3D body: height 0.36, standoff -0.04, extent -3.799,-1.822 -3.4,-1.428
3D body: height 0.36, standoff -0.04, extent -4.599,-1.822 -4.2,-1.428
3D body: height 0.36, standoff -0.04, extent 2.601,-1.822 3,-1.428
3D body: height 0.36, standoff -0.04, extent 1.801,-1.822 2.2,-1.428
3D body: height 0.36, standoff -0.04, extent 1.001,-1.822 1.4,-1.428
3D body: height 0.36, standoff -0.04, extent 3.401,-1.822 3.8,-1.428
3D body: height 0.36, standoff -0.04, extent 4.201,-1.822 4.6,-1.428
3D body: height 0.36, standoff -0.04, extent -1.399,-2.472 -1,-2.078
3D body: height 0.36, standoff -0.04, extent -2.199,-2.472 -1.8,-2.078
3D body: height 0.36, standoff -0.04, extent -2.999,-2.472 -2.6,-2.078
3D body: height 0.36, standoff -0.04, extent -3.799,-2.472 -3.4,-2.078
3D body: height 0.36, standoff -0.04, extent -4.599,-2.472 -4.2,-2.078
3D body: height 0.36, standoff -0.04, extent 2.601,-2.472 3,-2.078
3D body: height 0.36, standoff -0.04, extent 1.801,-2.472 2.2,-2.078
3D body: height 0.36, standoff -0.04, extent 1.001,-2.472 1.4,-2.078
3D body: height 0.36, standoff -0.04, extent 3.401,-2.472 3.8,-2.078
3D body: height 0.36, standoff -0.04, extent 4.201,-2.472 4.6,-2.078
3D body: height 1.06, standoff 1.05, extent -4.7,6.525 -4.1,7.125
